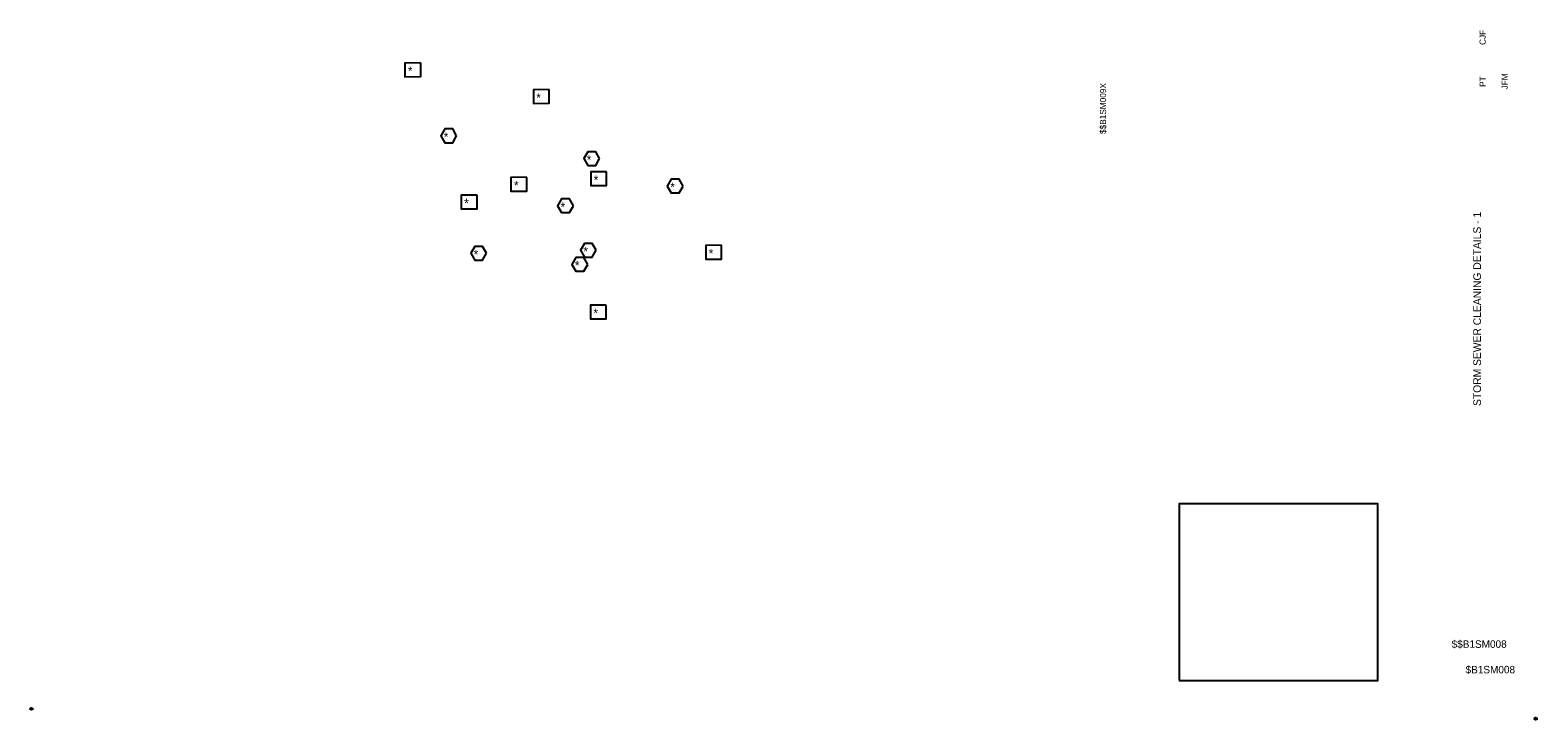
# Model space of a CAD drawing. Extents: x -0.2 to 34.1, y 0 to 15.7.
import ezdxf

# ---------------------------------------------------------------- set-up
doc = ezdxf.new("R2010")
doc.units = 0
for name, color, linetype in [('Default', 7, 'Continuous'), ('SC_Scratch1', 7, 'Continuous'), ('SH_Data', 7, 'Continuous')]:
    doc.layers.add(name, color=color, linetype=linetype)

msp = doc.modelspace()

# ---------------------------------------------------------------- linework, layer by layer
at = {"layer": 'Default'}
for p, q in [((-0.169, 0.28), (-0.117, 0.28)), ((-0.143, 0.28), (-0.094, 0.28)), ((34.012, 0.056), (34.064, 0.056)), ((34.039, 0.056), (34.088, 0.056))]:
    msp.add_line(p, q, dxfattribs=at)
msp.add_lwpolyline([(25.936, 0.92), (30.45, 0.92), (30.45, 4.931), (25.936, 4.931)], close=True, dxfattribs=at)
for centre in [(-0.143, 0.28), (34.038, 0.056)]:
    msp.add_circle(centre, 0.026, dxfattribs=at)
at = {"layer": 'SC_Scratch1'}
for points in [[(8.705, 14.947), (8.346, 14.943), (8.346, 14.632), (8.705, 14.636)], [(11.624, 14.34), (11.264, 14.336), (11.264, 14.025), (11.624, 14.029)], [(9.521, 13.29), (9.432, 13.446), (9.252, 13.446), (9.162, 13.29), (9.252, 13.134), (9.432, 13.134)], [(12.77, 12.774), (12.68, 12.93), (12.5, 12.93), (12.41, 12.774), (12.5, 12.619), (12.68, 12.619)], [(11.115, 12.348), (10.756, 12.345), (10.756, 12.033), (11.115, 12.037)], [(12.928, 12.475), (12.568, 12.471), (12.568, 12.159), (12.928, 12.163)], [(14.668, 12.15), (14.578, 12.306), (14.398, 12.306), (14.308, 12.15), (14.398, 11.994), (14.578, 11.994)], [(9.986, 11.944), (9.626, 11.94), (9.626, 11.629), (9.986, 11.633)], [(12.175, 11.702), (12.085, 11.858), (11.905, 11.858), (11.815, 11.702), (11.905, 11.546), (12.085, 11.546)], [(10.202, 10.625), (10.112, 10.78), (9.932, 10.78), (9.842, 10.625), (9.932, 10.469), (10.112, 10.469)], [(12.694, 10.691), (12.604, 10.847), (12.424, 10.847), (12.334, 10.691), (12.424, 10.536), (12.604, 10.536)], [(15.542, 10.804), (15.182, 10.8), (15.182, 10.489), (15.542, 10.492)], [(12.5, 10.372), (12.41, 10.527), (12.23, 10.527), (12.14, 10.372), (12.23, 10.216), (12.41, 10.216)], [(12.921, 9.448), (12.562, 9.444), (12.562, 9.132), (12.921, 9.136)]]:
    msp.add_lwpolyline(points, close=True, dxfattribs=at)

# ---------------------------------------------------------------- texts
at = {"layer": 'Default'}
for s, p in [('####', (-0.148, 0.271)), ('2', (-0.145, 0.287)), ('Ref', (-0.11, 0.287)), ('Engr 1:1', (-0.11, 0.271)), ('####', (34.034, 0.046)), ('1', (34.038, 0.063)), ('Drawing', (34.071, 0.063)), ('Engr 1:1', (34.071, 0.046))]:
    msp.add_text(s, height=0.00328, dxfattribs=at).set_placement(p)
at = {"layer": 'SC_Scratch1'}
for p in [(8.413, 14.663), (11.331, 14.056), (9.229, 13.166), (12.477, 12.65), (12.635, 12.19), (10.823, 12.064), (14.375, 12.026), (9.693, 11.66), (11.882, 11.577), (9.909, 10.5), (12.401, 10.567), (15.249, 10.52), (12.207, 10.247), (12.629, 9.164)]:
    msp.add_text('*', height=0.2, dxfattribs=at).set_placement(p)
msp.add_text('$$B1SM009X', height=0.14, rotation=90, dxfattribs=at).set_placement((24.278, 13.332))
at = {"layer": 'SH_Data'}
for s, height, p in [('CJF', 0.14, (32.903, 15.353)), ('PT', 0.14, (32.903, 14.401)), ('JFM', 0.14, (33.403, 14.344)), ('STORM SEWER CLEANING DETAILS - 1', 0.175, (32.796, 7.156))]:
    msp.add_text(s, height=height, rotation=90, dxfattribs=at).set_placement(p)
for s, p in [('$$B1SM008', (32.129, 1.665)), ('$B1SM008', (32.445, 1.085))]:
    msp.add_text(s, height=0.17, dxfattribs=at).set_placement(p)

doc.saveas('drawing.dxf')
